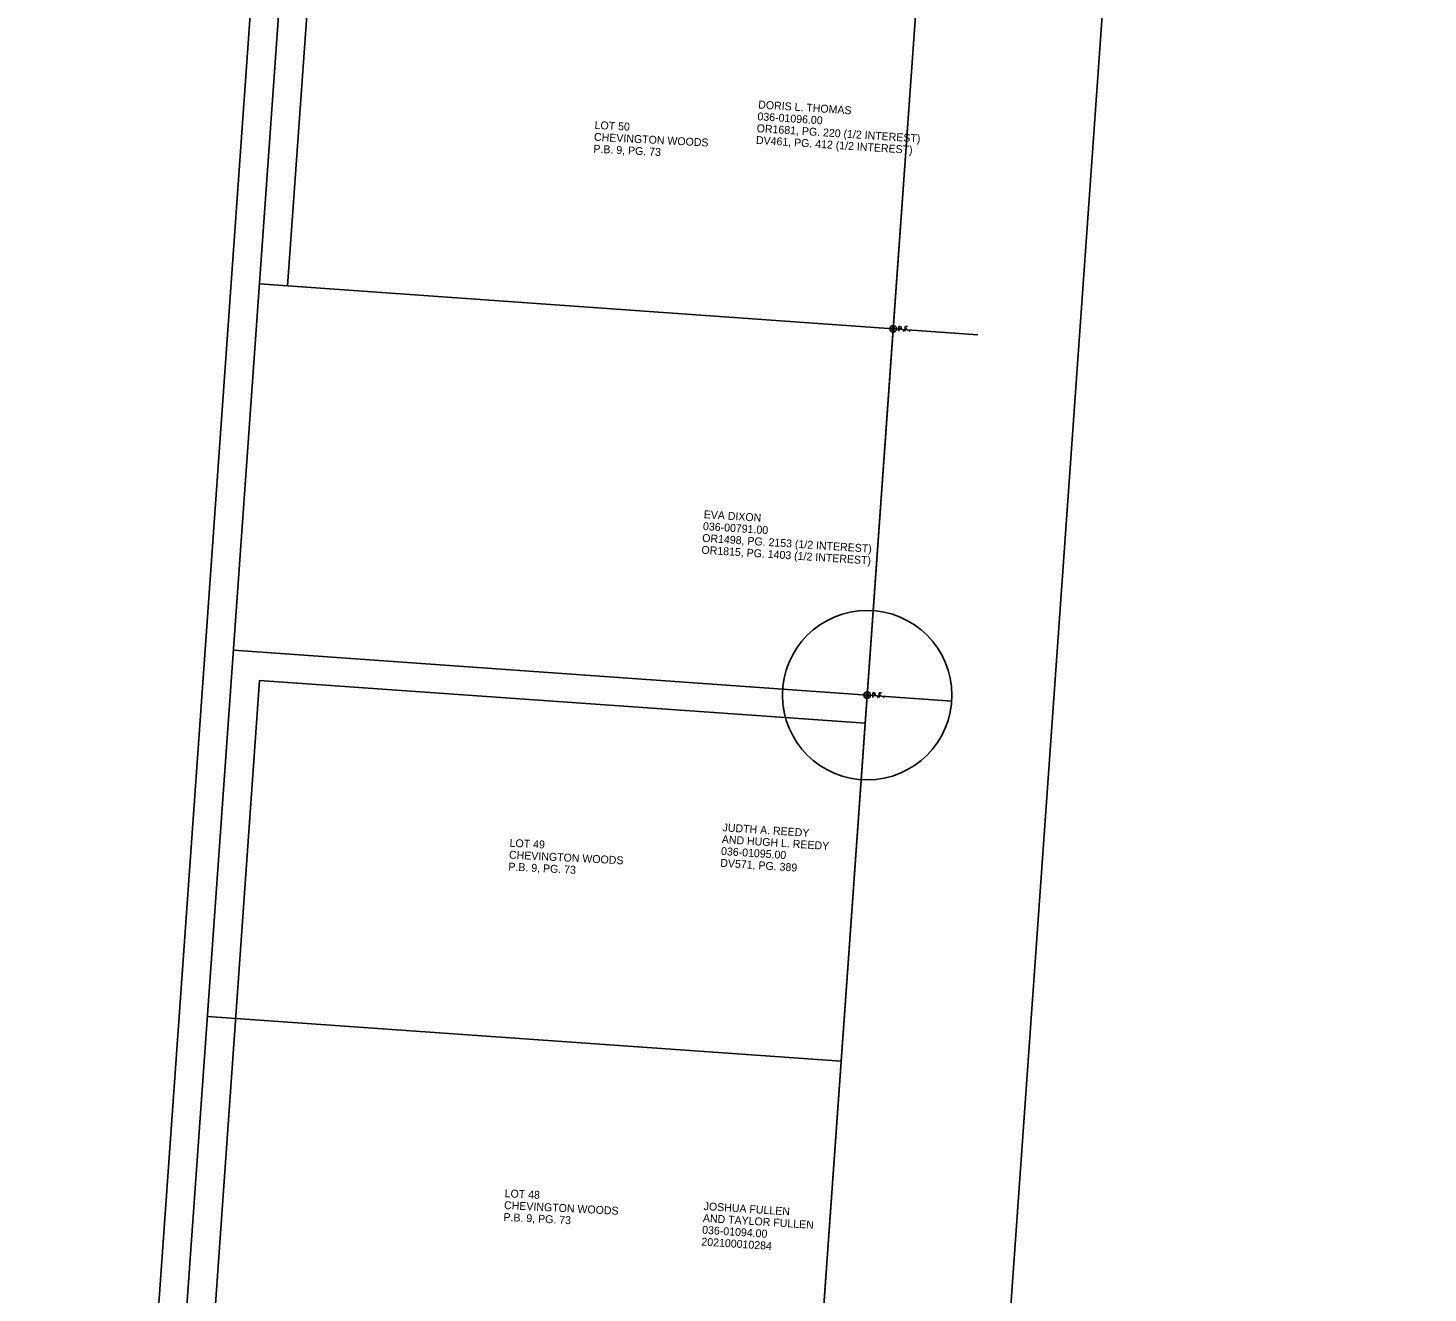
# Model space of a CAD drawing. Extents: x 1898254 to 1901377, y 701554 to 704886.
# Drawn here: x 1899449.8 to 1899945.6, y 702471.6 to 702919.7 of the extents above; entities that cross this region are included whole.
import ezdxf

# ---------------------------------------------------------------- set-up
doc = ezdxf.new("R2010")
doc.units = 0
for name, color, linetype in [('DV_X_Property_Line', 7, 'Continuous'), ('DV_X_Text', 7, 'Continuous'), ('RW_X_Esmt_General', 7, 'Continuous'), ('RW_X_Esmt_SH', 7, 'Continuous'), ('RW_X_Esmt_U', 7, 'Continuous'), ('RW_X_Fee_RW', 7, 'Continuous'), ('SC_Scratch1', 7, 'Continuous'), ('SC_Scratch2', 7, 'Continuous'), ('SC_Scratch5', 7, 'Continuous'), ('SV_X_Mon_Cells_Found', 7, 'Continuous')]:
    doc.layers.add(name, color=color, linetype=linetype)

msp = doc.modelspace()

# ---------------------------------------------------------------- linework, layer by layer
at = {"layer": 'DV_X_Property_Line'}
for p, q in [((1899476.33, 702046.99), (1899540.91, 702958.62)), ((1899531.73, 702829.02), (1899786.09, 702811)), ((1899522.54, 702699.25), (1899776.9, 702681.23)), ((1899513.35, 702569.58), (1899737.79, 702553.68))]:
    msp.add_line(p, q, dxfattribs=at)
at = {"layer": 'RW_X_Esmt_General'}
msp.add_line((1899550.18, 702947.94), (1899541.7, 702828.32), dxfattribs=at)
msp.add_lwpolyline([(1899746.27, 702673.38), (1899531.81, 702688.57), (1899514.85, 702449.17), (1899729.31, 702433.98)], dxfattribs=at)
at = {"layer": 'RW_X_Esmt_SH'}
msp.add_line((1899746.97, 702683.35), (1899756.17, 702813.12), dxfattribs=at)
at = {"layer": 'RW_X_Esmt_U'}
msp.add_lwpolyline([(1898413.09, 703063.91), (1899458.32, 702989.59), (1899455.83, 702954.62), (1899530.23, 702949.35), (1899466.62, 702051.43)], dxfattribs=at)
at = {"layer": 'RW_X_Fee_RW'}
for p, q in [((1899782.31, 703182.1), (1899756.17, 702813.12)), ((1899745.58, 701729.7), (1899846.72, 703157.34)), ((1899756.17, 702813.12), (1899786.09, 702811))]:
    msp.add_line(p, q, dxfattribs=at)
msp.add_lwpolyline([(1899746.97, 702683.35), (1899728.6, 702424), (1899758.53, 702421.88)], dxfattribs=at)
at = {"layer": 'SC_Scratch1'}
msp.add_circle((1899746.97, 702683.35), 30, dxfattribs=at)
at = {"layer": 'SC_Scratch2'}
msp.add_circle((1899815.76, 703229.84), 1561.35, dxfattribs=at)
at = {"layer": 'SC_Scratch5'}
for p, q in [((1899782.31, 703182.1), (1899700.34, 702025)), ((1899745.58, 701729.7), (1899846.72, 703157.34))]:
    msp.add_line(p, q, dxfattribs=at)
at = {"layer": 'SV_X_Mon_Cells_Found'}
for points in [[(1899758.2, 702812.32), (1899758.2, 702813.92), (1899758.73, 702813.92), (1899758.79, 702813.91), (1899758.86, 702813.88), (1899758.9, 702813.86), (1899758.93, 702813.83), (1899758.97, 702813.77), (1899759.01, 702813.71), (1899759.03, 702813.6), (1899759.03, 702813.45), (1899759.02, 702813.4), (1899759, 702813.33), (1899758.95, 702813.24), (1899758.91, 702813.2), (1899758.87, 702813.18), (1899758.82, 702813.15), (1899758.73, 702813.14), (1899758.2, 702813.14)], [(1899761.21, 702813.92), (1899760.45, 702813.92), (1899760.45, 702812.32)], [(1899759.84, 702812.53), (1899759.9, 702812.53), (1899759.93, 702812.51), (1899759.97, 702812.46), (1899759.97, 702812.4), (1899759.93, 702812.34), (1899759.9, 702812.32), (1899759.84, 702812.32), (1899759.81, 702812.34), (1899759.78, 702812.4), (1899759.78, 702812.46), (1899759.81, 702812.51), (1899759.84, 702812.53)], [(1899760.45, 702813.14), (1899760.99, 702813.14)], [(1899761.99, 702812.53), (1899762.05, 702812.53), (1899762.08, 702812.51), (1899762.11, 702812.46), (1899762.11, 702812.4), (1899762.08, 702812.34), (1899762.05, 702812.32), (1899761.99, 702812.32), (1899761.96, 702812.34), (1899761.93, 702812.4), (1899761.93, 702812.46), (1899761.96, 702812.51), (1899761.99, 702812.53)], [(1899748.97, 702682.55), (1899748.97, 702684.15), (1899749.5, 702684.15), (1899749.56, 702684.14), (1899749.63, 702684.12), (1899749.67, 702684.09), (1899749.7, 702684.07), (1899749.74, 702684), (1899749.78, 702683.94), (1899749.8, 702683.84), (1899749.8, 702683.69), (1899749.79, 702683.64), (1899749.77, 702683.56), (1899749.72, 702683.47), (1899749.68, 702683.44), (1899749.64, 702683.41), (1899749.59, 702683.39), (1899749.5, 702683.37), (1899748.97, 702683.37)], [(1899750.61, 702682.77), (1899750.67, 702682.77), (1899750.7, 702682.74), (1899750.74, 702682.69), (1899750.74, 702682.63), (1899750.7, 702682.58), (1899750.67, 702682.55), (1899750.61, 702682.55), (1899750.58, 702682.58), (1899750.55, 702682.63), (1899750.55, 702682.69), (1899750.58, 702682.74), (1899750.61, 702682.77)], [(1899751.98, 702684.15), (1899751.22, 702684.15), (1899751.22, 702682.55)], [(1899751.22, 702683.37), (1899751.76, 702683.37)], [(1899752.76, 702682.77), (1899752.82, 702682.77), (1899752.85, 702682.74), (1899752.88, 702682.69), (1899752.88, 702682.63), (1899752.85, 702682.58), (1899752.82, 702682.55), (1899752.76, 702682.55), (1899752.73, 702682.58), (1899752.7, 702682.63), (1899752.7, 702682.69), (1899752.73, 702682.74), (1899752.76, 702682.77)]]:
    msp.add_lwpolyline(points, dxfattribs=at)
for centre, radius in [((1899756.2, 702813.12), 1.2), ((1899756.2, 702813.12), 0.495), ((1899746.97, 702683.35), 1.2), ((1899746.97, 702683.35), 0.495)]:
    msp.add_circle(centre, radius, dxfattribs=at)

# ---------------------------------------------------------------- texts
at = {"layer": 'DV_X_Text'}
for s, rotation, p in [('DORIS L. THOMAS', 356.3351, (1899708.31, 702891.23)), ('036-01096.00', 356.3351, (1899708.04, 702887.04)), ('LOT 50', 357.0949, (1899650.39, 702883.96)), ('OR1681, PG. 220 (1/2 INTEREST)', 356.3351, (1899707.77, 702882.85)), ('P.B. 9, PG. 73', 357.0949, (1899649.96, 702875.57)), ('CHEVINGTON WOODS', 357.0949, (1899650.18, 702879.77)), ('DV461, PG. 412 (1/2 INTEREST)', 356.3351, (1899707.51, 702878.66)), ('EVA DIXON', 356.3351, (1899689.01, 702746.07)), ('036-00791.00', 356.3351, (1899688.75, 702741.88)), ('OR1498, PG. 2153 (1/2 INTEREST)', 356.3351, (1899688.48, 702737.69)), ('OR1815, PG. 1403 (1/2 INTEREST)', 356.3351, (1899688.21, 702733.5)), ('JUDTH A. REEDY', 356.3351, (1899695.68, 702635.15)), ('LOT 49', 357.0949, (1899620.28, 702629.66)), ('AND HUGH L. REEDY', 356.3351, (1899695.41, 702630.96)), ('CHEVINGTON WOODS', 357.0949, (1899620.07, 702625.47)), ('DV571, PG. 389', 356.3351, (1899694.88, 702622.58)), ('036-01095.00', 356.3351, (1899695.14, 702626.77)), ('P.B. 9, PG. 73', 357.0949, (1899619.85, 702621.27)), ('LOT 48', 357.0949, (1899618.54, 702505.53)), ('CHEVINGTON WOODS', 357.0949, (1899618.33, 702501.33)), ('JOSHUA FULLEN', 356.3351, (1899688.99, 702500.98)), ('P.B. 9, PG. 73', 357.0949, (1899618.11, 702497.14)), ('AND TAYLOR FULLEN', 356.3351, (1899688.72, 702496.79)), ('202100010284', 356.3351, (1899688.19, 702488.41)), ('036-01094.00', 356.3351, (1899688.46, 702492.6))]:
    msp.add_text(s, height=2.8, rotation=rotation, dxfattribs=at).set_placement(p)

doc.saveas('drawing.dxf')
